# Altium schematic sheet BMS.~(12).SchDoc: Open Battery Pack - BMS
size A3; Date: 26/03/2019; Author: Morgane Vallée - Samuel Lesueur; Revision: 1.0; SheetNumber: 1; SheetTotal: 3
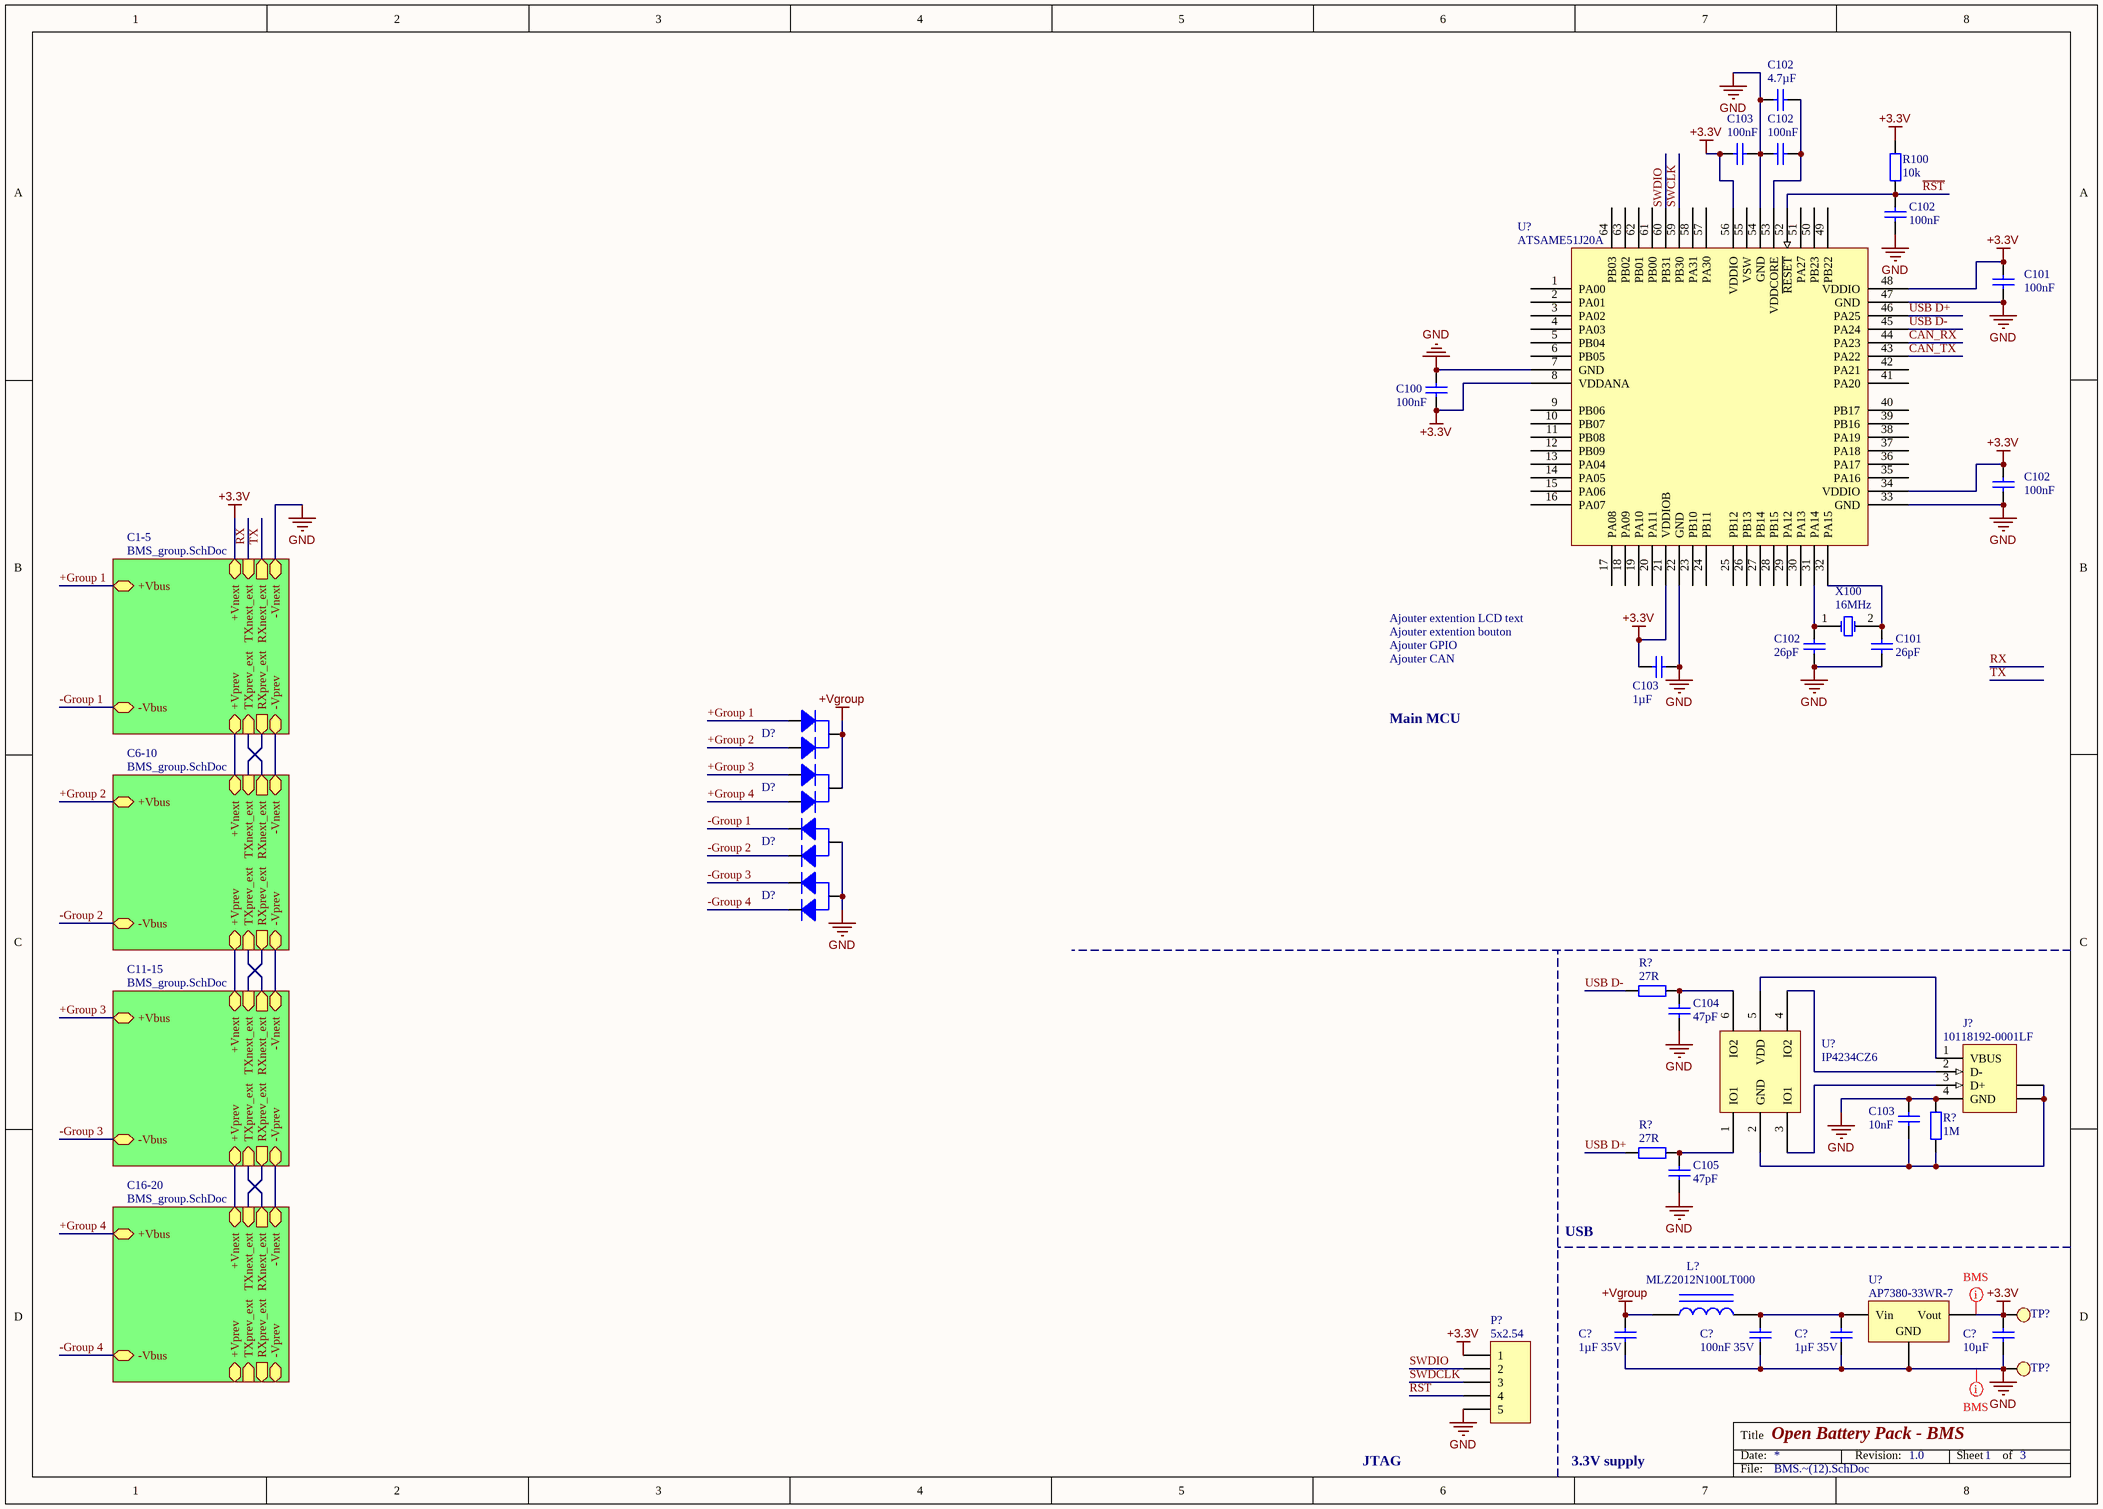
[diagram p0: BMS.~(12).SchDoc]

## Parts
(Parts that share a designator on the sheet are numbered #1, #2 ... from top to bottom, then left to right.)
C100  100nF  [C0603]
C101#1  100nF  [C0603]
C101#2  26pF  [C0603]
C102#1  4.7µF  [C0603]
C102#2  100nF  [C0603]
C102#3  100nF  [C0603]
C102#4  100nF  [C0603]
C102#5  26pF  [C0603]
C103#1  100nF  [C0603]
C103#2  1µF  [C0603]
C103#3  10nF  [C0603]
C104  47pF  [C0603]
C105  47pF  [C0603]
C?#1  1µF 35V  [C0603]
C?#2  100nF 35V  [C0603]
C?#3  1µF 35V  [C0603]
C?#4  10µF  [C0603]
D?#1  (no value)  [DIODES SOT-23-3]
D?#2  (no value)  [DIODES SOT-23-3]
D?#3  (no value)  [DIODES SOT-23-3]
D?#4  (no value)  [DIODES SOT-23-3]
J?  10118192-0001LF  [353576]
L?  MLZ2012N100LT000  [AXIAL-0.9]
P?  5x2.54  [HDR1X5]
R100  10k  [R0603]
R?#1  27R  [R0603]
R?#2  1M  [R0603]
R?#3  27R  [R0603]
TP?#1  Test Point  [Test Point]  (value not drawn)
TP?#2  Test Point  [Test Point]  (value not drawn)
U?#1  ATSAME51J20A  [TQFP-64N]
U?#2  IP4234CZ6  [VISHAY TSOP-6 MO-193C]
U?#3  AP7380-33WR-7  [DIODES SOT-23-5 W5]
X100  16MHz  [ABRACON ABLS]

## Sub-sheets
C1-5 = BMS_group.SchDoc: -Vprev, RXnext_ext (out), +Vnext, -Vnext, TXnext_ext (in), RXprev_ext (out), +Vprev, TXprev_ext (in), -Vbus, +Vbus
C6-10 = BMS_group.SchDoc: -Vprev, RXnext_ext (out), +Vnext, -Vnext, TXnext_ext (in), RXprev_ext (out), +Vprev, TXprev_ext (in), -Vbus, +Vbus
C11-15 = BMS_group.SchDoc: -Vprev, RXnext_ext (out), +Vnext, -Vnext, TXnext_ext (in), RXprev_ext (out), +Vprev, TXprev_ext (in), -Vbus, +Vbus
C16-20 = BMS_group.SchDoc: -Vprev, RXnext_ext (out), +Vnext, -Vnext, TXnext_ext (in), RXprev_ext (out), +Vprev, TXprev_ext (in), -Vbus, +Vbus

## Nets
+3.3V: C100.1 C101#1.2 C102#4.2 C103#1.2 C103#2.2 C?#4.1 P?.1 R100.2 TP?#1.1 U?#1.8(VDDANA) U?#1.21(VDDIOB) U?#1.34(VDDIO) U?#1.48(VDDIO) U?#1.56(VDDIO) U?#3.3(Vout) ; sheet C1-5/+Vnext
+Vgroup: C?#1.1 D?#1.3(K) D?#2.3(K) L?.1
GND: C100.2 C101#1.1 C101#2.1 C102#1.2 C102#2.2 C102#3.1 C102#4.1 C102#5.1 C103#1.1 C103#2.1 C103#3.2 C104.1 C105.1 C?#1.2 C?#2.2 C?#3.2 C?#4.2 D?#3.3(A) D?#4.3(A) J?.4(GND) P?.5 R?#2.1 TP?#2.1 U?#1.7(GND) U?#1.22(GND) U?#1.33(GND) U?#1.47(GND) U?#1.54(GND) U?#3.2(GND) ; sheet C1-5/-Vnext
+Group 1: D?#1.1(A1) ; sheet C1-5/+Vbus
+Group 2: D?#1.2(A2) ; sheet C6-10/+Vbus
+Group 3: D?#2.1(A1) ; sheet C11-15/+Vbus
+Group 4: D?#2.2(A2) ; sheet C16-20/+Vbus
-Group 1: D?#3.2(K2) ; sheet C1-5/-Vbus
-Group 2: D?#3.1(K1) ; sheet C6-10/-Vbus
-Group 3: D?#4.2(K2) ; sheet C11-15/-Vbus
-Group 4: D?#4.1(K1) ; sheet C16-20/-Vbus
CAN_RX: U?#1.44(PA23)
CAN_TX: U?#1.43(PA22)
~{RST}: C102#3.2 P?.4 R100.1 U?#1.52(~{RESET})
SWCLK: U?#1.59(PB30)
SWDCLK: P?.3
SWDIO: P?.2 U?#1.60(PB31)
USB D+: R?#3.1 U?#1.46(PA25)
USB D-: R?#1.1 U?#1.45(PA24)
NetC101#2_2: C101#2.2 U?#1.32(PA15) X100.2(OSC2)
NetC102#1_1: C102#1.1 C102#2.1 U?#1.53(VDDCORE)
NetC102#5_2: C102#5.2 U?#1.31(PA14) X100.1(OSC1)
NetC103#3_1: C103#3.1 J?.5(SHLD) J?.6(SHLD) R?#2.2 U?#2.2(GND)
NetC104_2: C104.2 R?#1.2 U?#2.6(IO2)
NetC105_2: C105.2 R?#3.2 U?#2.1(IO1)
NetC?#2_1: C?#2.1 C?#3.1 L?.2 U?#3.1(Vin)
NetJ?_1: J?.1(VBUS) U?#2.5(VDD)
NetJ?_2: J?.2(D-) U?#2.4(IO2)
NetJ?_3: J?.3(D+) U?#2.3(IO1)
(unnamed): sheet C1-5/-Vprev, sheet C6-10/-Vnext
(unnamed): sheet C1-5/RXprev_ext, sheet C6-10/TXnext_ext  [a separate net that carries the same name]
(unnamed): sheet C1-5/+Vprev, sheet C6-10/+Vnext  [a separate net that carries the same name]
(unnamed): sheet C1-5/TXprev_ext, sheet C6-10/RXnext_ext  [a separate net that carries the same name]
(unnamed): sheet C6-10/-Vprev, sheet C11-15/-Vnext  [a separate net that carries the same name]
(unnamed): sheet C6-10/RXprev_ext, sheet C11-15/TXnext_ext  [a separate net that carries the same name]
(unnamed): sheet C6-10/+Vprev, sheet C11-15/+Vnext  [a separate net that carries the same name]
(unnamed): sheet C6-10/TXprev_ext, sheet C11-15/RXnext_ext  [a separate net that carries the same name]
(unnamed): sheet C11-15/-Vprev, sheet C16-20/-Vnext  [a separate net that carries the same name]
(unnamed): sheet C11-15/RXprev_ext, sheet C16-20/TXnext_ext  [a separate net that carries the same name]
(unnamed): sheet C11-15/+Vprev, sheet C16-20/+Vnext  [a separate net that carries the same name]
(unnamed): sheet C11-15/TXprev_ext, sheet C16-20/RXnext_ext  [a separate net that carries the same name]

Not connected (* = marked no-connect by the designer): U?#1 1(PA00) 2(PA01) 3(PA02) 4(PA03) 5(PB04) 6(PB05) 9(PB06) 10(PB07) 11(PB08) 12(PB09) 13(PA04) 14(PA05) 15(PA06) 16(PA07) 17(PA08) 18(PA09) 19(PA10) 20(PA11) 23(PB10) 24(PB11) 25(PB12) 26(PB13) 27(PB14) 28(PB15) 29(PA12) 30(PA13) 35(PA16) 36(PA17) 37(PA18) 38(PA19) 39(PB16) 40(PB17) 41(PA20) 42(PA21) 49(PB22) 50(PB23) 51(PA27) 55(VSW) 57(PA30) 58(PA31) 61(PB00) 62(PB01) 63(PB02) 64(PB03)

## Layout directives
net class BMS: +3.3V, GND

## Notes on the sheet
- Ajouter extention LCD text
- Ajouter extention bouton
- Ajouter GPIO
- Main MCU
- Ajouter CAN
- USB
- JTAG
- 3.3V supply

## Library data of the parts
C100 C101#1 C101#2 C102#1-C102#5 C103#1-C103#3 C104 C105 C?#1-C?#4 = Cap: Capacitor
D?#1 D?#2 = Diode dual C: Diode 2 common Cathode
D?#3 D?#4 = Diode dual A: Diode 2 common Anode
J? = 1-353576-1: USB 1.1, Right Angle, SMT, A Type, Receptacle, 4 Position, White
L? = Inductor Iron: Magnetic-Core Inductor
P? = Header 5: Header, 5-Pin
R100 R?#1-R?#3 = Res2: Resistor
U?#2 = IP4234CZ6: Single USB 2.0 ESD protection to IEC 61000-4-2 level 4
U?#3 = Volt Reg: Voltage Regulator
X100 = XTAL: Crystal Oscillator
